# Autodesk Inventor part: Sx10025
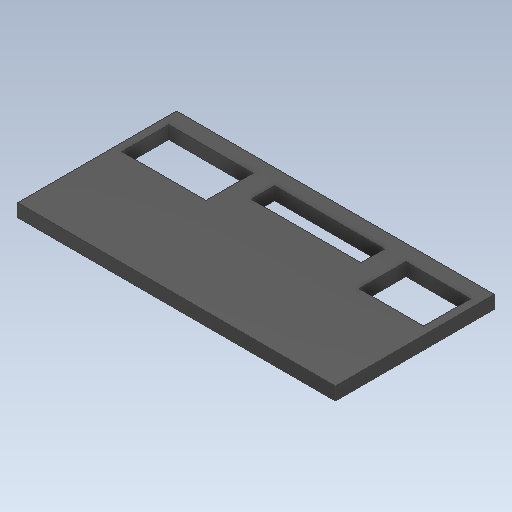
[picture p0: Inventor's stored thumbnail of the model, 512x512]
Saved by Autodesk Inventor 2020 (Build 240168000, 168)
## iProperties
Created: 2021-02
Part Number: Sx10025
Material: Generico
Document SubType Name: Modeling
Designer: zambolin
Density: 1 g/cm^3
Appearance: Default
Author: zambolin
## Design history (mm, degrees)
feature "Solido2"
node "Solido1"
